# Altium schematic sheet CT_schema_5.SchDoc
size 334 x 183 mm
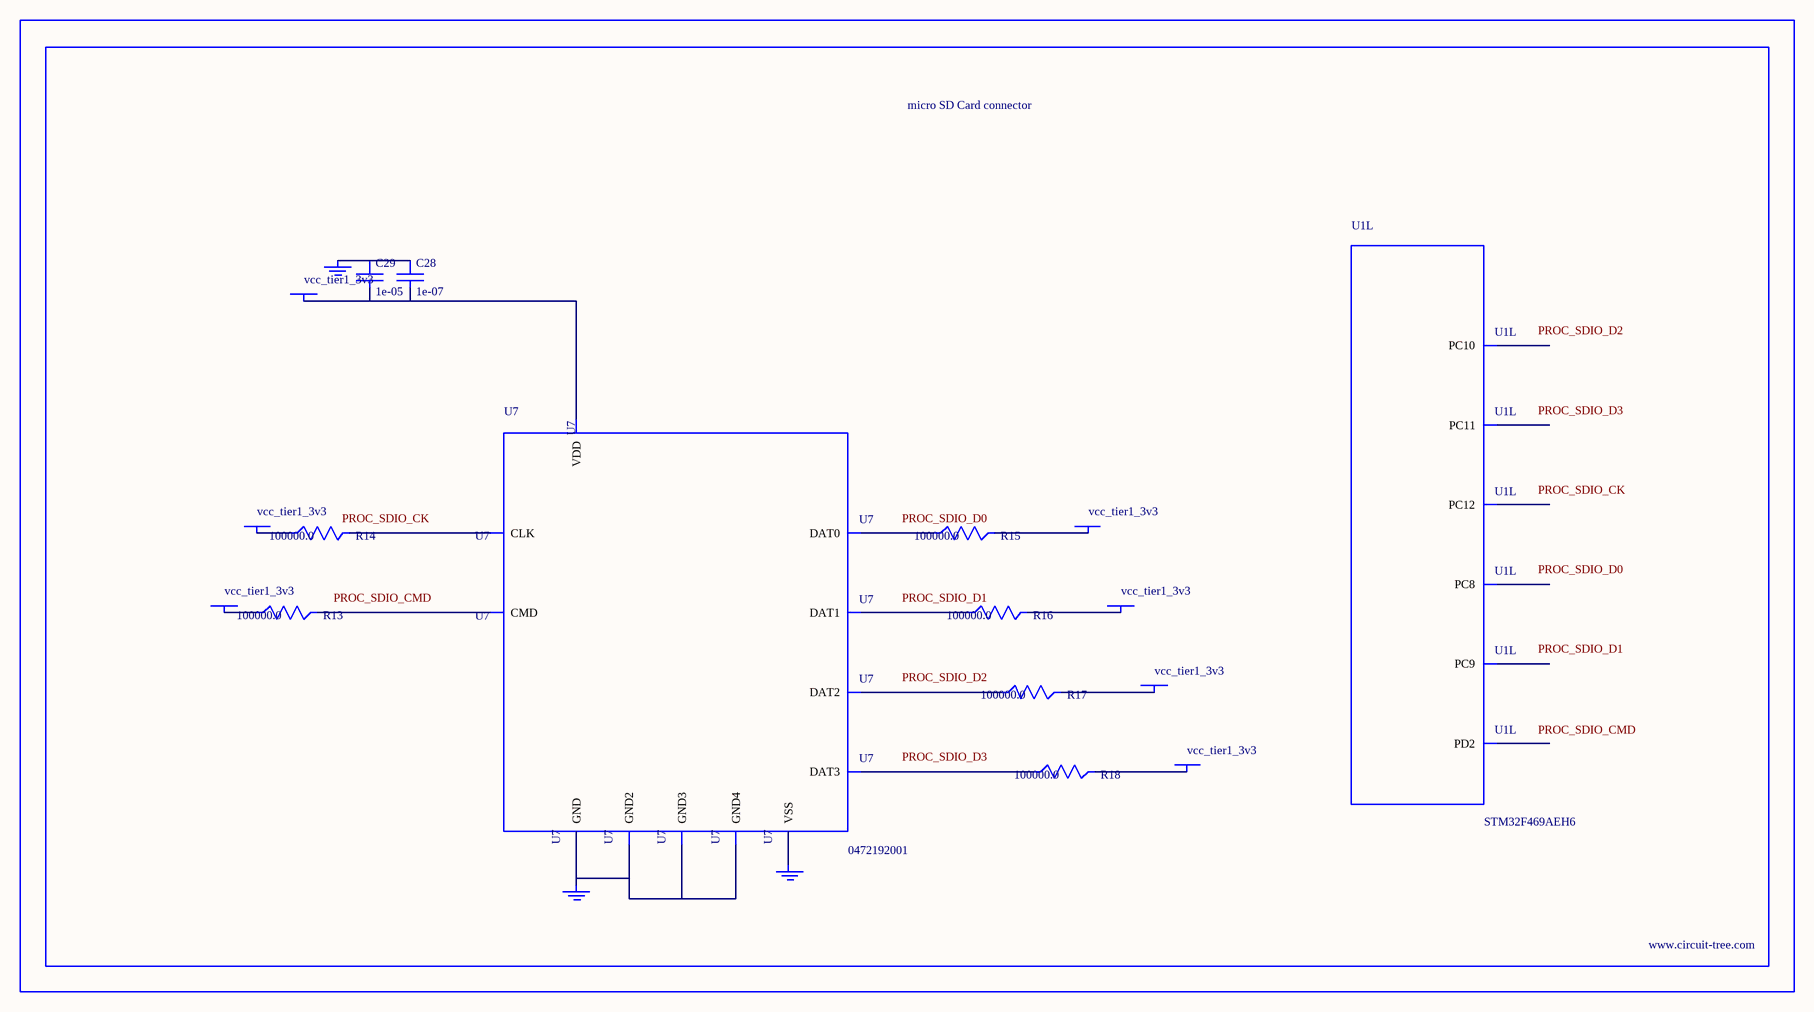
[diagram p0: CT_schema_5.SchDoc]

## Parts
BORDER4  (no value)
C28  1e-07  [C0402]
C29  1e-05  [C0805]
GND_INSTANCE_4_0  (no value)
GND_INSTANCE_4_1  (no value)
GND_INSTANCE_4_2  (no value)
POWER_INSTANCE_4_0  vcc_tier1_3v3
POWER_INSTANCE_4_1  vcc_tier1_3v3
POWER_INSTANCE_4_2  vcc_tier1_3v3
POWER_INSTANCE_4_3  vcc_tier1_3v3
POWER_INSTANCE_4_4  vcc_tier1_3v3
POWER_INSTANCE_4_5  vcc_tier1_3v3
POWER_INSTANCE_4_6  vcc_tier1_3v3
R13  100000.0  [R0603]
R14  100000.0  [R0603]
R15  100000.0  [R0603]
R16  100000.0  [R0603]
R17  100000.0  [R0603]
R18  100000.0  [R0603]
U1  STM32F469AEH6  [UFBGA169]  (part L of 14)
U7  0472192001  [MOLEX_47219-2001]

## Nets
NetC28_1: C28.1 C29.1 GND_INSTANCE_4_0.0(GND)
NetC28_2: C28.2 C29.2 POWER_INSTANCE_4_3.0(PWR) U7.4(VDD)
NetGND_INSTANCE_4_1_0: GND_INSTANCE_4_1.0(GND) U7.6(VSS)
NetGND_INSTANCE_4_2_0: GND_INSTANCE_4_2.0(GND) U7.G1(GND) U7.G2(GND2) U7.G3(GND3) U7.G4(GND4)
NetPOWER_INSTANCE_4_0_0: POWER_INSTANCE_4_0.0(PWR) R17.2
NetPOWER_INSTANCE_4_1_0: POWER_INSTANCE_4_1.0(PWR) R18.2
NetPOWER_INSTANCE_4_2_0: POWER_INSTANCE_4_2.0(PWR) R13.1
NetPOWER_INSTANCE_4_4_0: POWER_INSTANCE_4_4.0(PWR) R14.1
NetPOWER_INSTANCE_4_5_0: POWER_INSTANCE_4_5.0(PWR) R15.2
NetPOWER_INSTANCE_4_6_0: POWER_INSTANCE_4_6.0(PWR) R16.2
NetR13_2: R13.2 U7.3(CMD)
NetR14_2: R14.2 U7.5(CLK)
NetR15_1: R15.1 U7.7(DAT0)
NetR16_1: R16.1 U7.8(DAT1)
NetR17_1: R17.1 U7.1(DAT2)
NetR18_1: R18.1 U7.2(DAT3)

Not connected (* = marked no-connect by the designer): U1 A9(PC12) B8(PD2) B9(PC11) C10(PC10) E10(PC8) G10(PC9)

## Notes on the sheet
- Labels drawn without touching a wire or pin: PROC_SDIO_CK, PROC_SDIO_CMD, PROC_SDIO_D0, PROC_SDIO_D1, PROC_SDIO_D2, PROC_SDIO_D3

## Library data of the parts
BORDER4 = BORDER_PAGE4
C28 = C0402C104K3RACTU
C29 = C0805C106K8RACTU
GND_INSTANCE_4_0-GND_INSTANCE_4_2 = GND
POWER_INSTANCE_4_0-POWER_INSTANCE_4_6 = PWR
R13-R18 = RC0603JR-07100KL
